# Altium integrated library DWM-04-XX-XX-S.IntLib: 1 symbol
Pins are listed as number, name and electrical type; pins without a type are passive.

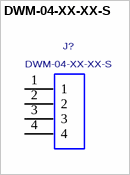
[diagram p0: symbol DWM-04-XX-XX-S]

## DWM-04-XX-XX-S
designator J?
BOARD SPACING MICRO STRIPS.; MANUFACTURER: SAMTEC
footprint DWM-04-XX-XX-S
pins: 1, 2, 3, 4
